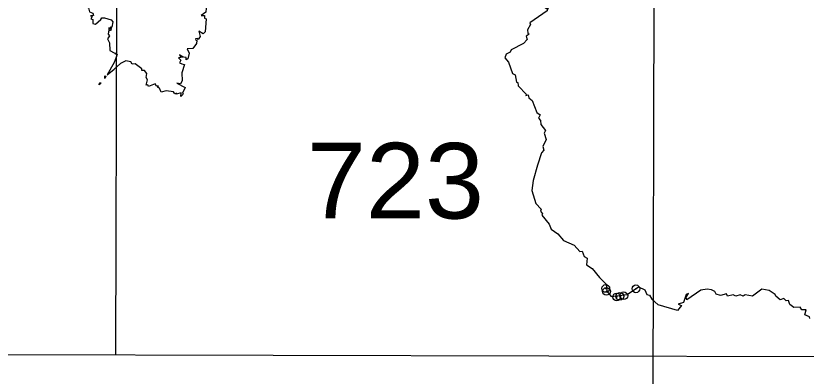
# Model space of a CAD drawing. Extents: x 480264 to 484872, y 4381275 to 4384491.
# Drawn here: x 484367.1 to 484571, y 4383250.8 to 4383343.7 of the extents above; entities that cross this region are included whole.
import ezdxf
from ezdxf.enums import TextEntityAlignment as Align

# ---------------------------------------------------------------- set-up
doc = ezdxf.new("R2010")
doc.units = 0
doc.header["$LTSCALE"] = 4
doc.header["$PDMODE"] = 32
doc.header["$PDSIZE"] = 2
doc.linetypes.add('DOTTED', pattern=[1.5, 0.3, -1.2])
for name, color, linetype, lineweight in [('1', 7, 'Continuous', 13), ('2', 7, 'DOTTED', 13), ('3', 7, 'Continuous', 25)]:
    doc.layers.add(name, color=color, linetype=linetype, lineweight=lineweight)

msp = doc.modelspace()

# ---------------------------------------------------------------- linework, layer by layer
at = {"layer": '1', "lineweight": 25}
for p, q in [((484392.94, 4383256.25), (484393.8, 4383617.56)), ((484531.07, 4383075.28), (484532.36, 4383617.23)), ((484254.38, 4383256.58), (484808.62, 4383255.26))]:
    msp.add_line(p, q, dxfattribs=at)
at = {"layer": '3'}
for points in [[(484384.04, 4383347.21), (484383.89, 4383346.15), (484385.14, 4383346.22), (484385.89, 4383345.76), (484386.16, 4383344.8), (484387.02, 4383344.41), (484387.21, 4383343.78), (484386.4, 4383343.73), (484386.85, 4383343.58), (484386.52, 4383342.95), (484387, 4383342.8), (484387.02, 4383341.72), (484387.71, 4383341.56), (484389.08, 4383342.79)], [(484416, 4383346.96), (484416.28, 4383346.72), (484416.16, 4383344.7), (484414.97, 4383343.79), (484415.79, 4383343.83), (484415.76, 4383343.15), (484416.2, 4383342.94), (484415.96, 4383339.6), (484415.45, 4383339.1), (484414.38, 4383339.77), (484414.66, 4383338.38), (484414.18, 4383337.62), (484414, 4383337.92), (484413.48, 4383337.77), (484413.59, 4383337.47)], [(484504.01, 4383346.39), (484504.6, 4383346.08), (484504.28, 4383345.53), (484503.62, 4383345.89), (484504.28, 4383345.42), (484504.17, 4383344.98), (484499.67, 4383341.91), (484499.85, 4383341.46), (484499.12, 4383340.16), (484499.19, 4383339.24), (484499.53, 4383339.02), (484498.78, 4383338.5), (484499, 4383337.61), (484498.05, 4383336.58)], [(484389.08, 4383342.79), (484389.3, 4383343.24), (484390.02, 4383343.24), (484391.71, 4383342.69), (484392.14, 4383342.19), (484391.88, 4383340.81), (484391.55, 4383340.85), (484391.9, 4383340.73), (484391.5, 4383340.6), (484391.82, 4383340.44), (484391.52, 4383340.47), (484391.71, 4383340.02), (484391.29, 4383339.83), (484391.23, 4383340.71), (484390.97, 4383338.96), (484391.28, 4383338.54), (484390.8, 4383337.82), (484391.33, 4383336.75), (484391.4, 4383334.78), (484392.53, 4383334.22)], [(484413.59, 4383337.47), (484413.86, 4383337.36), (484413.72, 4383336.58), (484412.83, 4383335.31), (484411.33, 4383335.22), (484411.84, 4383334.09), (484411.5, 4383332.64), (484411.08, 4383332.39), (484411.07, 4383333.02), (484409.8, 4383333.12), (484410.3, 4383333.19), (484409.37, 4383333.67), (484409.66, 4383332.97), (484409.14, 4383332.91), (484409.66, 4383332.26), (484409.34, 4383331.57), (484409.97, 4383331.35)], [(484498.05, 4383336.58), (484494.9, 4383334.96), (484494.59, 4383334.33), (484493.59, 4383333.82), (484493.25, 4383332.91), (484494.18, 4383331.81), (484495.26, 4383328.86), (484495.9, 4383328.48), (484496.3, 4383326.62), (484496.61, 4383326.52)], [(484392.53, 4383334.22), (484393.13, 4383334.13), (484392.72, 4383334.01), (484393.25, 4383333.72), (484392.51, 4383331.67)], [(484392.51, 4383331.67), (484390.71, 4383328.54), (484392.5, 4383329.93)], [(484399.61, 4383330.02), (484397.93, 4383331.33), (484397.14, 4383331.28), (484396.82, 4383331.88), (484395.53, 4383332.08), (484394.14, 4383331.41), (484392.5, 4383329.93)], [(484409.97, 4383331.35), (484410.67, 4383331.21), (484409.96, 4383328.99), (484410.04, 4383326.94), (484409.59, 4383326.19), (484408.67, 4383326.32), (484410.82, 4383325.25), (484410.11, 4383323.79), (484410.33, 4383323.5), (484409.73, 4383322.95), (484409.75, 4383323.85), (484408.51, 4383323.53), (484408.6, 4383323.79), (484408.17, 4383323.62), (484407.78, 4383324.16)], [(484407.78, 4383324.16), (484405.96, 4383324.41), (484404.63, 4383324), (484404.2, 4383325.1), (484403.68, 4383325.3), (484403.98, 4383325.57), (484403.45, 4383325.62), (484403.05, 4383326.17), (484401.32, 4383325.5), (484401.2, 4383325.93), (484400.77, 4383325.83), (484401.12, 4383327.21), (484400.72, 4383327.82), (484400.94, 4383328.82), (484400.32, 4383329.64), (484399.63, 4383329.66), (484399.61, 4383330.02)], [(484496.61, 4383326.52), (484496.7, 4383325.66), (484498.84, 4383323.45), (484498.7, 4383323.19), (484499.29, 4383323.33), (484499.44, 4383322.58), (484500.34, 4383321.93), (484501.49, 4383318.79)], [(484501.49, 4383318.79), (484502.35, 4383318.16), (484501.94, 4383317.36), (484502.48, 4383316.74), (484502.51, 4383315.72), (484503.7, 4383314.15), (484503.35, 4383313.44), (484503.94, 4383311.82), (484503.04, 4383310.05), (484503.3, 4383309.08), (484502.68, 4383308.36), (484501.65, 4383305.21), (484500.59, 4383301.24)], [(484500.59, 4383301.24), (484500.21, 4383298.71), (484501.27, 4383295.35), (484502.65, 4383293.87), (484502.42, 4383293.3), (484502.99, 4383292.69), (484502.83, 4383292.34), (484504.71, 4383290), (484505.22, 4383288.71), (484506.91, 4383287.52)], [(484506.91, 4383287.52), (484508.34, 4383285.79), (484511.17, 4383284.6), (484512.61, 4383282.92), (484513.18, 4383283.01), (484513.74, 4383281.68), (484514.45, 4383281.18), (484514.3, 4383279.5), (484515.8, 4383278.51), (484517.69, 4383276.2)], [(484517.69, 4383276.2), (484519.34, 4383274.5), (484519.57, 4383272.72), (484520.63, 4383271.36), (484524.82, 4383271.85), (484527.7, 4383273.83), (484529.36, 4383273.05), (484529.88, 4383271.84), (484530.54, 4383271.66), (484531.19, 4383270.61)], [(484543.8, 4383272.92), (484540.21, 4383270.47), (484539.97, 4383271.19), (484540.62, 4383272.07), (484540.05, 4383271.84), (484539.31, 4383269.76), (484537.94, 4383269.34), (484538.83, 4383269), (484537.76, 4383267.75), (484532.82, 4383269.16), (484531.19, 4383270.61)], [(484563.09, 4383271.43), (484562.98, 4383271.85), (484561.39, 4383272.83), (484559.54, 4383273.19), (484557.11, 4383271.4), (484555.19, 4383271.77), (484554.72, 4383271.37), (484553.92, 4383271.71), (484552.78, 4383271.37), (484552.1, 4383271.75), (484550.67, 4383271.44), (484550.44, 4383272.03), (484548.89, 4383271.56), (484547.78, 4383271.94), (484547.41, 4383272.63), (484546.57, 4383273.02), (484545.4, 4383273.22), (484543.8, 4383272.92)], [(484571.91, 4383265.68), (484571.84, 4383266.04), (484570.63, 4383266.57), (484570.95, 4383267.9), (484569.86, 4383267.86), (484569.39, 4383268.57), (484567.75, 4383268.5), (484566.73, 4383269.24), (484566.44, 4383270.32), (484565.81, 4383270.18), (484565.16, 4383270.8), (484564.28, 4383270.43), (484563.09, 4383271.43)]]:
    msp.add_lwpolyline(points, dxfattribs=at)
for points in [[(484390.06, 4383328.21), (484390.39, 4383328.14), (484390.1, 4383327.56)], [(484388.96, 4383326.54), (484388.99, 4383326.18), (484388.52, 4383325.97)]]:
    msp.add_lwpolyline(points, close=True, dxfattribs=at)
for p in [(484519.28, 4383273.4), (484527.05, 4383273.3), (484519.46, 4383272.63), (484522.1, 4383271.21), (484522.91, 4383271.37), (484523.93, 4383271.51)]:
    msp.add_point(p, dxfattribs=at)

# ---------------------------------------------------------------- texts
at = {"layer": '2', "width": 1.05}
msp.add_text('723', height=19.5, rotation=359.864, dxfattribs=at).set_placement((484465.012, 4383291.464), align=Align.CENTER)

doc.saveas('drawing.dxf')
